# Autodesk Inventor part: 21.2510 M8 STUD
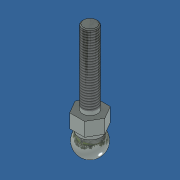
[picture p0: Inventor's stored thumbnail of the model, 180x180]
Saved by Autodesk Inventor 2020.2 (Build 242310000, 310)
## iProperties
Created: 2008-03
Document SubType Name: Modeling
Designer: Oster
Material: Stahl
Description: 21.2510 M8 STUD
Part Number: 21.2510 M8 STUD
Mass: 40.6007 g
Surface Area: 22.6004 cm^2
Volume: 5.17207 cm^3
Density: 7.85 g/cm^3
Appearance: Zink
Beschreibung: Kugelschraube M08x40 MT
Bezeichnung: Kugelschraube M08x40 MT
Artikelnr: 212901/0
Lieferantennr: 72401
Zeichnungsnr: 21-2901-0FZ.000
MiniTec_ID: 212901/0
Teileart: K
Lieferant: MiniTec
Title: Kugelschraube M08x40 MT
Author: Andy Moles
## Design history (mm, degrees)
revolve "Revolution1" stored, may be unused: angle "d1" = 90 deg
sketch "Sketch2"
  geometry: C1 r 6 at (0, 0); 1 further point
  constraints: 1 centre point, 1 coincident
  dimensions: "d2" = 12 diameter of C1
extrude "Extrusion1" join sketch "Sketch2" distance "d3" = 7; taper "d4" = 0 deg
sketch "Sketch3"
  geometry: L1 (-4.041, 7)-(4.041, 7); L2 (4.041, 7)-(8.083, 0); L3 (8.083, 0)-(4.041, -7); L4 (4.041, -7)-(-4.041, -7); L5 (-4.041, -7)-(-8.083, 0); L6 (-8.083, 0)-(-4.041, 7); C1 r 6 at (0, 0) reference; 1 further point
  constraints: 12 end point, 5 equal length, 1 horizontal, 1 horizontal alignment, 1 midpoint, 1 parallel, 1 vertical alignment
  dimensions: "d6" = 120 deg angle of L6 L5; "d7" = 120 deg angle of L1 L6; "d8" = 14 distance between parallel lines of L4 L1
extrude "Extrusion2" join sketch "Sketch3" distance "d9" = 7.5; taper "d10" = 0 deg
sketch "Sketch4"
  geometry: C1 r 4 at (0, 0); 1 further point
  constraints: 1 centre point, 1 coincident
  dimensions: "d11" = 8 diameter of C1
extrude "Extrusion3" join sketch "Sketch4" distance "d12" = 40.5; taper "d13" = 0 deg
thread "Thread1" dims "d14" = 38.5, "d15" = 2
chamfer "Chamfer1" distance "d16" = 0.5; stored, may be unused: second distance "d17" = 2, angle "d18" = 45 deg
node "Volumenkörper1"
node "Volumenkörpern"
node "Oberflächenkörpern"
sketch "Sketch1"
  geometry: L1 (0, -7.5)-(0, 7.5); A1 r 7.5 centre (0, 0) between (0, -7.5) and (0, 7.5); 1 further point
  constraints: 2 end point, 2 point on circle, 1 centre point, 1 coincident, 1 midpoint, 1 vertical
  dimensions: "d5" = 15 distance of L1.start L1.end
